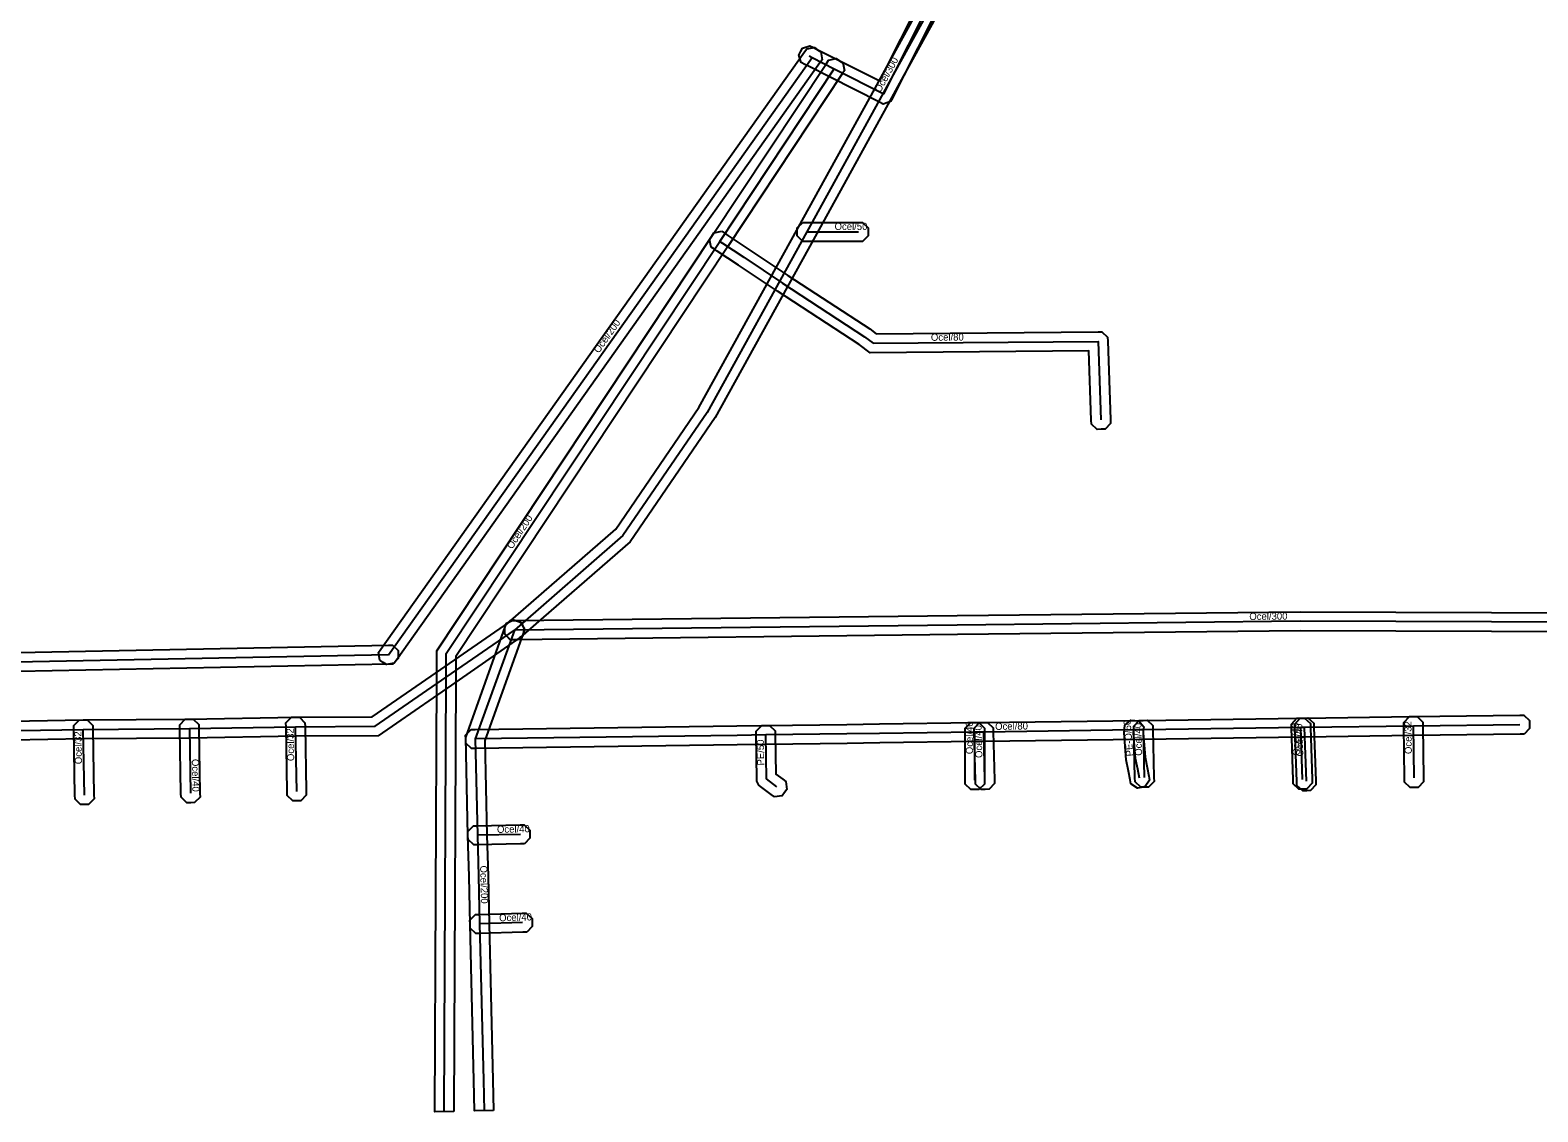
# Model space of a CAD drawing. Extents: x -702844 to -702342, y -1011731 to -1011542.
# Drawn here: x -702588.2 to -702429.5, y -1011724.1 to -1011610.2 of the extents above; entities that cross this region are included whole.
import ezdxf

# ---------------------------------------------------------------- set-up
doc = ezdxf.new("R2010")
doc.units = 0
for name, color, linetype in [('1', 7, 'Continuous'), ('14', 7, 'Continuous'), ('18', 7, 'Continuous'), ('20', 7, 'Continuous'), ('24', 7, 'Continuous'), ('30', 7, 'Continuous')]:
    doc.layers.add(name, color=color, linetype=linetype)

msp = doc.modelspace()

# ---------------------------------------------------------------- linework, layer by layer
at = {"layer": '1'}
for points in [[(-702466.97, -1011557.14), (-702496.24, -1011615.01), (-702497.44, -1011617.37), (-702497.63, -1011617.74), (-702498.02, -1011617.87), (-702498.41, -1011618), (-702498.78, -1011617.81), (-702504, -1011615.17), (-702506.33, -1011613.99), (-702506.65, -1011613.83), (-702507.02, -1011613.64), (-702507.28, -1011612.86), (-702507.09, -1011612.49), (-702506.9, -1011612.12), (-702506.11, -1011611.86), (-702505.74, -1011612.05), (-702505.43, -1011612.21), (-702503.1, -1011613.39), (-702498.77, -1011615.57), (-702498.03, -1011614.1), (-702468.76, -1011556.23)], [(-702479.59, -1011584.8), (-702496.26, -1011615.04), (-702497.54, -1011617.36), (-702505.57, -1011631.94), (-702516.08, -1011650.99), (-702525.03, -1011664.09), (-702536.57, -1011674.12), (-702536.88, -1011674.4), (-702537.71, -1011674.34), (-702537.98, -1011674.02), (-702538.25, -1011673.71), (-702538.19, -1011672.89), (-702537.88, -1011672.61), (-702526.54, -1011662.75), (-702517.79, -1011649.94), (-702507.33, -1011630.97), (-702499.29, -1011616.39), (-702498.01, -1011614.07), (-702481.35, -1011583.85)], [(-702424.31, -1011673.54), (-702454.53, -1011673.44), (-702490.6, -1011673.84), (-702537.21, -1011674.37), (-702537.63, -1011674.37), (-702538.22, -1011673.79), (-702538.22, -1011673.38), (-702538.23, -1011672.96), (-702537.65, -1011672.37), (-702537.23, -1011672.37), (-702490.62, -1011671.84), (-702454.54, -1011671.44), (-702424.31, -1011671.54)], [(-702593.91, -1011683.01), (-702582.59, -1011682.82), (-702571.43, -1011682.73), (-702560.25, -1011682.54), (-702552.17, -1011682.49), (-702544.96, -1011677.5), (-702537.79, -1011672.55), (-702537.45, -1011672.31), (-702536.64, -1011672.46), (-702536.4, -1011672.8), (-702536.17, -1011673.14), (-702536.32, -1011673.96), (-702536.66, -1011674.19), (-702543.82, -1011679.15), (-702551.54, -1011684.49), (-702560.23, -1011684.54), (-702571.4, -1011684.73), (-702582.56, -1011684.82), (-702593.87, -1011685.01)]]:
    msp.add_lwpolyline(points, dxfattribs=at)
for points in [[(-702551.5, -1011675.71), (-702551.26, -1011675.37), (-702506.69, -1011612.52), (-702506.45, -1011612.18), (-702505.64, -1011612.04), (-702505.3, -1011612.28), (-702504.96, -1011612.52), (-702504.82, -1011613.34), (-702505.06, -1011613.68), (-702549.63, -1011676.52), (-702549.87, -1011676.86), (-702550.69, -1011677), (-702551.03, -1011676.76), (-702551.36, -1011676.52)], [(-702543.59, -1011724.02), (-702545.59, -1011724.06), (-702545.39, -1011678.32), (-702545.38, -1011675.54), (-702516.44, -1011631.9), (-702504.38, -1011613.72), (-702504.15, -1011613.38), (-702503.34, -1011613.21), (-702503, -1011613.44), (-702502.65, -1011613.67), (-702502.49, -1011614.48), (-702502.72, -1011614.83), (-702514.77, -1011633.01), (-702543.38, -1011676.14), (-702543.39, -1011678.33)], [(-702506.86, -1011630.45), (-702506.45, -1011630.45), (-702500.99, -1011630.45), (-702500.58, -1011630.45), (-702499.99, -1011631.04), (-702499.99, -1011631.45), (-702499.99, -1011631.87), (-702500.58, -1011632.45), (-702500.99, -1011632.45), (-702506.45, -1011632.45), (-702506.86, -1011632.45), (-702507.45, -1011631.87), (-702507.45, -1011631.45), (-702507.45, -1011631.04)], [(-702515.4, -1011631.39), (-702515.05, -1011631.62), (-702514.76, -1011631.82), (-702512.53, -1011633.3), (-702508.44, -1011636.03), (-702499.8, -1011641.67), (-702499.13, -1011642.17), (-702475.79, -1011641.99), (-702475.38, -1011641.98), (-702474.8, -1011642.55), (-702474.78, -1011642.95), (-702474.5, -1011651.19), (-702474.49, -1011651.61), (-702475.05, -1011652.21), (-702475.47, -1011652.23), (-702475.88, -1011652.24), (-702476.49, -1011651.68), (-702476.5, -1011651.26), (-702476.75, -1011643.99), (-702499.78, -1011644.17), (-702500.94, -1011643.32), (-702509.54, -1011637.7), (-702513.63, -1011634.97), (-702515.86, -1011633.48), (-702516.16, -1011633.29), (-702516.5, -1011633.06), (-702516.67, -1011632.25), (-702516.44, -1011631.9), (-702516.21, -1011631.56)], [(-702539.4, -1011723.91), (-702541.4, -1011723.96), (-702541.48, -1011720.76), (-702541.88, -1011704.31), (-702541.99, -1011699.3), (-702542.1, -1011694.98), (-702542.34, -1011684.66), (-702538.17, -1011673.03), (-702538.03, -1011672.64), (-702537.28, -1011672.29), (-702536.89, -1011672.43), (-702536.5, -1011672.57), (-702536.14, -1011673.32), (-702536.28, -1011673.71), (-702540.34, -1011684.98), (-702540.1, -1011694.93), (-702539.99, -1011699.25), (-702539.88, -1011704.26), (-702539.48, -1011720.72)], [(-702802.41, -1011681.9), (-702843.99, -1011682.6), (-702844.1, -1011680.6), (-702802.44, -1011679.9), (-702794.94, -1011679.78), (-702550.47, -1011674.95), (-702550.05, -1011674.94), (-702549.46, -1011675.51), (-702549.45, -1011675.93), (-702549.44, -1011676.34), (-702550.01, -1011676.94), (-702550.43, -1011676.95), (-702794.91, -1011681.78)], [(-702583.45, -1011691.15), (-702583.46, -1011690.74), (-702583.58, -1011683.84), (-702583.58, -1011683.42), (-702583.01, -1011682.83), (-702582.59, -1011682.82), (-702582.18, -1011682.81), (-702581.58, -1011683.39), (-702581.58, -1011683.8), (-702581.46, -1011690.7), (-702581.45, -1011691.12), (-702582.03, -1011691.71), (-702582.44, -1011691.72), (-702582.86, -1011691.73)], [(-702570.42, -1011683.3), (-702570.42, -1011683.71), (-702570.3, -1011690.51), (-702570.29, -1011690.93), (-702570.87, -1011691.52), (-702571.28, -1011691.53), (-702571.7, -1011691.54), (-702572.29, -1011690.96), (-702572.3, -1011690.55), (-702572.42, -1011683.75), (-702572.42, -1011683.33), (-702571.85, -1011682.74), (-702571.43, -1011682.73), (-702571.02, -1011682.72)], [(-702561.12, -1011690.77), (-702561.12, -1011690.35), (-702561.24, -1011683.55), (-702561.25, -1011683.14), (-702560.67, -1011682.54), (-702560.26, -1011682.54), (-702559.84, -1011682.53), (-702559.25, -1011683.11), (-702559.24, -1011683.52), (-702559.12, -1011690.32), (-702559.12, -1011690.73), (-702559.69, -1011691.33), (-702560.11, -1011691.34), (-702560.52, -1011691.34)], [(-702430.96, -1011684.31), (-702431.38, -1011684.32), (-702442.59, -1011684.47), (-702454.07, -1011684.62), (-702454.43, -1011684.63), (-702471, -1011684.86), (-702471.48, -1011684.86), (-702487.81, -1011685.09), (-702488.75, -1011685.1), (-702498.77, -1011685.24), (-702502.2, -1011685.29), (-702510.75, -1011685.4), (-702513.76, -1011685.44), (-702541.33, -1011685.82), (-702541.74, -1011685.83), (-702542.33, -1011685.25), (-702542.34, -1011684.84), (-702542.35, -1011684.42), (-702541.77, -1011683.83), (-702541.35, -1011683.82), (-702513.79, -1011683.44), (-702510.78, -1011683.4), (-702502.23, -1011683.29), (-702498.8, -1011683.24), (-702488.78, -1011683.1), (-702487.84, -1011683.09), (-702471.5, -1011682.86), (-702471.03, -1011682.86), (-702454.45, -1011682.63), (-702454.1, -1011682.62), (-702442.62, -1011682.47), (-702431.41, -1011682.32), (-702430.99, -1011682.31), (-702430.4, -1011682.89), (-702430.39, -1011683.3), (-702430.39, -1011683.71)], [(-702472.34, -1011689.53), (-702472.42, -1011689.12), (-702472.59, -1011688.2), (-702472.83, -1011687.02), (-702473.05, -1011684.17), (-702473.02, -1011683.77), (-702472.97, -1011683.36), (-702472.34, -1011682.84), (-702471.92, -1011682.88), (-702471.51, -1011682.92), (-702470.98, -1011683.56), (-702471.03, -1011683.97), (-702471.05, -1011684.19), (-702470.85, -1011686.74), (-702470.63, -1011687.82), (-702470.45, -1011688.75), (-702470.37, -1011689.16), (-702470.84, -1011689.84), (-702471.25, -1011689.92), (-702471.65, -1011690)], [(-702471.9, -1011689.33), (-702471.91, -1011688.92), (-702472.02, -1011683.88), (-702472.03, -1011683.46), (-702471.45, -1011682.87), (-702471.04, -1011682.86), (-702470.62, -1011682.85), (-702470.03, -1011683.42), (-702470.02, -1011683.84), (-702469.91, -1011688.87), (-702469.9, -1011689.29), (-702470.47, -1011689.89), (-702470.89, -1011689.89), (-702471.3, -1011689.9)], [(-702455.26, -1011689.54), (-702455.27, -1011689.12), (-702455.44, -1011683.66), (-702455.45, -1011683.25), (-702454.89, -1011682.64), (-702454.47, -1011682.63), (-702454.06, -1011682.62), (-702453.45, -1011683.19), (-702453.44, -1011683.6), (-702453.27, -1011689.06), (-702453.26, -1011689.47), (-702453.83, -1011690.08), (-702454.24, -1011690.09), (-702454.66, -1011690.1)], [(-702454.86, -1011689.72), (-702454.87, -1011689.31), (-702455.08, -1011683.66), (-702455.1, -1011683.25), (-702454.53, -1011682.64), (-702454.12, -1011682.63), (-702453.7, -1011682.61), (-702453.1, -1011683.17), (-702453.08, -1011683.59), (-702452.87, -1011689.24), (-702452.86, -1011689.65), (-702453.42, -1011690.26), (-702453.83, -1011690.27), (-702454.25, -1011690.29)], [(-702443.53, -1011689.35), (-702443.53, -1011688.94), (-702443.6, -1011683.48), (-702443.61, -1011683.07), (-702443.03, -1011682.47), (-702442.62, -1011682.47), (-702442.2, -1011682.46), (-702441.61, -1011683.04), (-702441.6, -1011683.46), (-702441.53, -1011688.91), (-702441.53, -1011689.33), (-702442.11, -1011689.92), (-702442.52, -1011689.92), (-702442.94, -1011689.93)], [(-702509.85, -1011690.91), (-702510.18, -1011690.66), (-702511.3, -1011689.82), (-702511.48, -1011689.68), (-702511.7, -1011689.26), (-702511.7, -1011689.03), (-702511.76, -1011684.42), (-702511.77, -1011684), (-702511.19, -1011683.41), (-702510.78, -1011683.4), (-702510.36, -1011683.4), (-702509.77, -1011683.97), (-702509.76, -1011684.39), (-702509.7, -1011688.51), (-702508.98, -1011689.06), (-702508.65, -1011689.31), (-702508.53, -1011690.13), (-702508.78, -1011690.46), (-702509.03, -1011690.79)], [(-702489.76, -1011689.56), (-702489.76, -1011689.15), (-702489.76, -1011684.1), (-702489.76, -1011683.69), (-702489.18, -1011683.1), (-702488.76, -1011683.1), (-702488.35, -1011683.1), (-702487.76, -1011683.69), (-702487.76, -1011684.1), (-702487.76, -1011689.15), (-702487.76, -1011689.56), (-702488.35, -1011690.15), (-702488.76, -1011690.15), (-702489.18, -1011690.15)], [(-702488.68, -1011689.58), (-702488.69, -1011689.16), (-702488.83, -1011684.11), (-702488.84, -1011683.7), (-702488.27, -1011683.1), (-702487.85, -1011683.09), (-702487.44, -1011683.08), (-702486.84, -1011683.65), (-702486.83, -1011684.06), (-702486.69, -1011689.11), (-702486.68, -1011689.52), (-702487.25, -1011690.12), (-702487.66, -1011690.14), (-702488.08, -1011690.15)], [(-702536.15, -1011695.85), (-702536.56, -1011695.86), (-702541.08, -1011695.95), (-702541.49, -1011695.96), (-702542.09, -1011695.39), (-702542.1, -1011694.97), (-702542.11, -1011694.56), (-702541.53, -1011693.96), (-702541.12, -1011693.95), (-702536.61, -1011693.86), (-702536.19, -1011693.85), (-702535.59, -1011694.42), (-702535.58, -1011694.84), (-702535.58, -1011695.25)], [(-702535.91, -1011705.14), (-702536.32, -1011705.15), (-702540.85, -1011705.29), (-702541.26, -1011705.3), (-702541.86, -1011704.73), (-702541.88, -1011704.32), (-702541.89, -1011703.9), (-702541.32, -1011703.3), (-702540.9, -1011703.29), (-702536.38, -1011703.15), (-702535.96, -1011703.14), (-702535.36, -1011703.71), (-702535.35, -1011704.12), (-702535.34, -1011704.54)]]:
    msp.add_lwpolyline(points, close=True, dxfattribs=at)
at = {"layer": '14'}
for points in [[(-702465.53, -1011556.33), (-702466.19, -1011557.57), (-702480.47, -1011584.33), (-702497.14, -1011614.55), (-702498.41, -1011616.87), (-702506.45, -1011631.45), (-702516.94, -1011650.46), (-702525.79, -1011663.42), (-702537.22, -1011673.37)], [(-702382.02, -1011671.61), (-702383.02, -1011671.63), (-702388.01, -1011671.69), (-702393.17, -1011671.75), (-702422.27, -1011672.53), (-702422.66, -1011672.54), (-702422.95, -1011672.55), (-702423.18, -1011672.54), (-702423.72, -1011672.54), (-702424.31, -1011672.54), (-702454.54, -1011672.44), (-702490.61, -1011672.84), (-702537.22, -1011673.37)], [(-702593.89, -1011684.01), (-702582.58, -1011683.82), (-702571.42, -1011683.73), (-702560.24, -1011683.54), (-702551.85, -1011683.49), (-702544.39, -1011678.33), (-702537.22, -1011673.37)], [(-702537.22, -1011673.37), (-702541.34, -1011684.82), (-702541.1, -1011694.95), (-702540.99, -1011699.27), (-702540.88, -1011704.29), (-702540.48, -1011720.74), (-702540.4, -1011723.94)], [(-702582.46, -1011690.72), (-702582.58, -1011683.82)], [(-702571.42, -1011683.73), (-702571.3, -1011690.53)], [(-702560.12, -1011690.34), (-702560.24, -1011683.54)], [(-702431.39, -1011683.32), (-702442.6, -1011683.47), (-702454.08, -1011683.62), (-702454.44, -1011683.63), (-702471.02, -1011683.86), (-702471.49, -1011683.86), (-702472.02, -1011683.87), (-702487.83, -1011684.09), (-702488.76, -1011684.1), (-702498.79, -1011684.24), (-702502.22, -1011684.29), (-702510.76, -1011684.4), (-702513.78, -1011684.44), (-702541.34, -1011684.82)], [(-702509.58, -1011689.86), (-702510.7, -1011689.02), (-702510.76, -1011684.4)], [(-702488.76, -1011689.15), (-702488.76, -1011684.1)], [(-702487.69, -1011689.14), (-702487.83, -1011684.09)], [(-702471.43, -1011688.94), (-702471.61, -1011688.01), (-702471.84, -1011686.88), (-702472.05, -1011684.18), (-702472.02, -1011683.87)], [(-702470.91, -1011688.89), (-702471.02, -1011683.86)], [(-702454.27, -1011689.09), (-702454.44, -1011683.63)], [(-702453.87, -1011689.27), (-702454.08, -1011683.62)], [(-702442.53, -1011688.92), (-702442.6, -1011683.47)], [(-702536.58, -1011694.86), (-702541.1, -1011694.95)], [(-702536.35, -1011704.15), (-702540.88, -1011704.29)]]:
    msp.add_lwpolyline(points, dxfattribs=at)
at = {"layer": '18'}
msp.add_lwpolyline([(-702506.45, -1011631.45), (-702500.99, -1011631.45)], dxfattribs=at)
at = {"layer": '24'}
for points in [[(-702506.2, -1011612.94), (-702505.88, -1011613.1), (-702503.55, -1011614.28), (-702498.33, -1011616.92), (-702497.14, -1011614.56), (-702467.86, -1011556.69), (-702461.73, -1011544.64), (-702460.05, -1011545.63), (-702442.84, -1011555.81)], [(-702550.45, -1011675.95), (-702505.88, -1011613.1)], [(-702544.59, -1011724.04), (-702544.39, -1011678.32), (-702544.38, -1011675.84), (-702515.6, -1011632.46), (-702503.55, -1011614.28)], [(-702515.6, -1011632.46), (-702515.31, -1011632.65), (-702513.08, -1011634.13), (-702508.99, -1011636.86), (-702500.37, -1011642.49), (-702499.46, -1011643.17), (-702475.78, -1011642.99), (-702475.5, -1011651.23)], [(-702550.45, -1011675.95), (-702794.92, -1011680.78), (-702802.43, -1011680.9), (-702844.04, -1011681.6)]]:
    msp.add_lwpolyline(points, dxfattribs=at)

# ---------------------------------------------------------------- texts
at = {"layer": '20'}
for s, rotation, p in [('Ocel/300', 61.1336, (-702498.71, -1011616.85)), ('Ocel/300', 0.6449, (-702459.87, -1011672.3)), ('PE-O/50', 94.4474, (-702472.08, -1011686.62)), ('Ocel/32', 90.9799, (-702582.72, -1011687.47)), ('Ocel/32', 90.9774, (-702560.38, -1011687.14)), ('Ocel/40', 90, (-702488.96, -1011686.42)), ('Ocel/40', 91.5322, (-702487.96, -1011686.81)), ('Ocel/80', 0.7866, (-702486.62, -1011683.87)), ('Ocel/40', 91.2286, (-702471.16, -1011686.58)), ('Ocel/40', 91.7519, (-702454.56, -1011686.56)), ('Ocel/40', 92.129, (-702454.18, -1011686.65)), ('Ocel/32', 90.7246, (-702442.77, -1011686.4)), ('PE/50', 90.7821, (-702510.92, -1011687.61)), ('Ocel/40', 270.9774, (-702571.16, -1011686.93)), ('Ocel/40', 1.1805, (-702539.04, -1011694.71)), ('Ocel/200', 271.3658, (-702540.82, -1011698.15)), ('Ocel/40', 1.6836, (-702538.81, -1011704.02))]:
    msp.add_text(s, height=0.75, rotation=rotation, dxfattribs=at).set_placement(p)
msp.add_text('Ocel/50', height=0.75, dxfattribs=at).set_placement((-702503.52, -1011631.25))
at = {"layer": '30'}
for s, rotation, p in [('Ocel/200', 54.6554, (-702528.33, -1011644.28)), ('Ocel/80', 0.4356, (-702493.38, -1011642.92)), ('Ocel/200', 56.4448, (-702537.46, -1011664.9))]:
    msp.add_text(s, height=0.75, rotation=rotation, dxfattribs=at).set_placement(p)

doc.saveas('drawing.dxf')
